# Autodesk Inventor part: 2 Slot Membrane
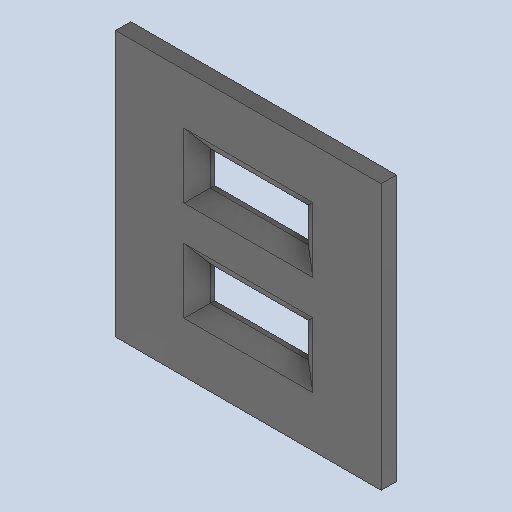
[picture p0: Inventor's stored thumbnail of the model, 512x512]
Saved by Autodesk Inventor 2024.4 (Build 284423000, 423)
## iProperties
Created: 2025-08
Part Number: 2 Slot Membrane
Material: Generic
Document SubType Name: Modeling
Designer: AdminForWorker
Density: 1 g/cm^3
Appearance: Default
Title: 2 Slot Membrane
Author: AdminForWorker
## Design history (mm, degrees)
feature "Body1"
body "Solid1"
